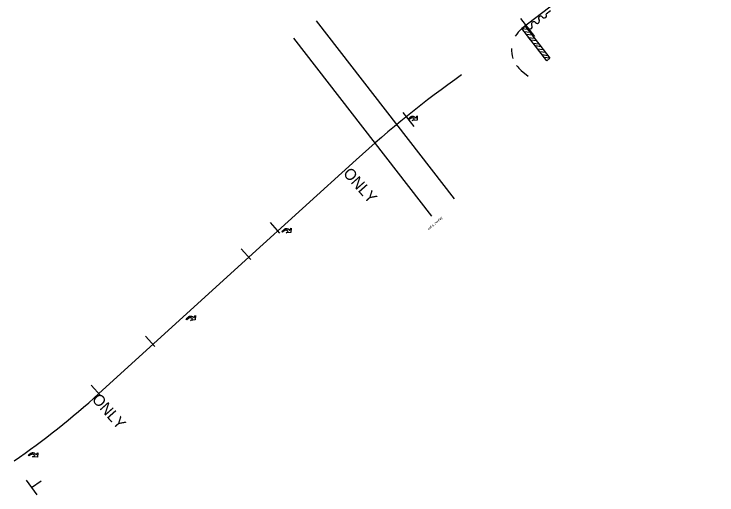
# Model space of a CAD drawing. Extents: x 857071 to 1646387, y 839649 to 1457497.
# Drawn here: x 1638861 to 1639485, y 842405 to 842832 of the extents above; entities that cross this region are included whole.
import ezdxf

# ---------------------------------------------------------------- set-up
doc = ezdxf.new("R2010")
doc.units = 0
for name, color, linetype in [('DEV CRASH CUSHION CELL', 7, 'Continuous'), ('DEV STATIONARY SIGN CELL', 7, 'Continuous'), ('DEV TYPE 3 BARRICADE CELL', 7, 'Continuous'), ('MARK RIGHT ONLY RIGHT SYMBOL CELL', 7, 'Continuous'), ('Prop Mkg 3ft Min Skp 9ft Wide White', 7, 'Continuous'), ('Prop Mkg Solid White Edge Line', 7, 'Continuous'), ('Prop Mkg Solid White Wide Lane Line', 7, 'Continuous'), ('Scratch_Level_0', 7, 'Continuous'), ('Scratch_Level_1', 7, 'Continuous'), ('Scratch_Level_2', 7, 'Continuous'), ('Scratch_Level_3', 7, 'Continuous'), ('Scratch_Level_4', 7, 'Continuous')]:
    doc.layers.add(name, color=color, linetype=linetype)

msp = doc.modelspace()

# ---------------------------------------------------------------- linework, layer by layer
at = {"layer": 'DEV CRASH CUSHION CELL'}
msp.add_line((1639337.59, 842834.49), (1639333.63, 842831.43), dxfattribs=at)
for centre, start, end in [((1639328.89, 842827.76), 37.7072, 217.7072), ((1639332.05, 842830.21), 217.7072, 37.7072), ((1639319.39, 842820.42), 217.7072, 37.7072), ((1639322.56, 842822.87), 37.7072, 217.7072), ((1639325.72, 842825.32), 217.7072, 37.7072)]:
    msp.add_arc(centre, 2, start, end, dxfattribs=at)
at = {"layer": 'DEV STATIONARY SIGN CELL'}
for p, q in [((1638872.01, 842417.87), (1638881.41, 842404.67)), ((1638876.75, 842411.22), (1638885.3, 842417.3))]:
    msp.add_line(p, q, dxfattribs=at)
at = {"layer": 'DEV TYPE 3 BARRICADE CELL'}
for p, q in [((1639312.16, 842818.62), (1639315, 842820.83)), ((1639317.17, 842818.03), (1639312.16, 842818.62)), ((1639312.2, 842818.66), (1639315, 842820.83)), ((1639334.25, 842790.22), (1639312.2, 842818.66)), ((1639314.14, 842816.06), (1639319.16, 842815.47)), ((1639316.12, 842813.5), (1639314.14, 842816.06)), ((1639315, 842820.83), (1639317.17, 842818.03)), ((1639315, 842820.83), (1639337.05, 842792.39)), ((1639319.16, 842815.47), (1639321.14, 842812.91)), ((1639321.14, 842812.91), (1639316.12, 842813.5)), ((1639318.11, 842810.94), (1639323.13, 842810.35)), ((1639320.09, 842808.38), (1639318.11, 842810.94)), ((1639323.13, 842810.35), (1639325.11, 842807.79)), ((1639325.11, 842807.79), (1639320.09, 842808.38)), ((1639322.07, 842805.82), (1639327.09, 842805.23)), ((1639324.06, 842803.27), (1639322.07, 842805.82)), ((1639329.08, 842802.67), (1639324.06, 842803.27)), ((1639327.09, 842805.23), (1639329.08, 842802.67)), ((1639326.04, 842800.71), (1639331.1, 842800.07)), ((1639328.03, 842798.15), (1639326.04, 842800.71)), ((1639333.08, 842797.51), (1639328.03, 842798.15)), ((1639331.1, 842800.07), (1639333.08, 842797.51)), ((1639330.01, 842795.59), (1639335.07, 842794.95)), ((1639331.99, 842793.03), (1639330.01, 842795.59)), ((1639337.05, 842792.39), (1639331.99, 842793.03)), ((1639337.05, 842792.39), (1639334.25, 842790.22)), ((1639335.07, 842794.95), (1639337.05, 842792.39))]:
    msp.add_line(p, q, dxfattribs=at)
at = {"layer": 'MARK RIGHT ONLY RIGHT SYMBOL CELL'}
for points in [[(1639211.7, 842737.61), (1639211.03, 842738.36), (1639212.96, 842740.08), (1639213.34, 842740.38), (1639213.65, 842740.57), (1639214.03, 842740.74), (1639214.39, 842740.83), (1639214.69, 842740.87), (1639215.13, 842740.87), (1639215.46, 842740.83), (1639215.84, 842740.77), (1639216.27, 842740.63), (1639216.58, 842740.48), (1639216.95, 842740.24), (1639217.4, 842739.86), (1639217.94, 842739.26), (1639219.17, 842741.25), (1639219.12, 842737.42), (1639214.74, 842737.08), (1639216.75, 842738.2), (1639216.31, 842738.7), (1639216.04, 842738.97), (1639215.74, 842739.16), (1639215.47, 842739.28), (1639215.09, 842739.4), (1639214.79, 842739.46), (1639214.36, 842739.43), (1639213.96, 842739.32), (1639213.58, 842739.18), (1639213.13, 842738.89)], [(1639099.62, 842637.92), (1639098.95, 842638.67), (1639100.88, 842640.39), (1639101.26, 842640.69), (1639101.57, 842640.88), (1639101.95, 842641.05), (1639102.31, 842641.14), (1639102.61, 842641.18), (1639103.05, 842641.18), (1639103.38, 842641.14), (1639103.76, 842641.08), (1639104.19, 842640.94), (1639104.5, 842640.79), (1639104.87, 842640.55), (1639105.32, 842640.17), (1639105.86, 842639.57), (1639107.09, 842641.56), (1639107.04, 842637.73), (1639102.66, 842637.39), (1639104.67, 842638.51), (1639104.23, 842639.01), (1639103.96, 842639.28), (1639103.66, 842639.47), (1639103.39, 842639.59), (1639103.01, 842639.71), (1639102.71, 842639.77), (1639102.28, 842639.74), (1639101.88, 842639.63), (1639101.5, 842639.49), (1639101.05, 842639.2)], [(1639014.69, 842560.2), (1639014.03, 842560.95), (1639015.96, 842562.66), (1639016.33, 842562.96), (1639016.64, 842563.16), (1639017.02, 842563.32), (1639017.38, 842563.41), (1639017.69, 842563.45), (1639018.12, 842563.46), (1639018.45, 842563.42), (1639018.83, 842563.35), (1639019.27, 842563.21), (1639019.57, 842563.06), (1639019.95, 842562.83), (1639020.39, 842562.45), (1639020.93, 842561.85), (1639022.16, 842563.84), (1639022.12, 842560), (1639017.73, 842559.67), (1639019.74, 842560.79), (1639019.3, 842561.29), (1639019.04, 842561.55), (1639018.74, 842561.75), (1639018.46, 842561.87), (1639018.08, 842561.99), (1639017.78, 842562.04), (1639017.36, 842562.02), (1639016.95, 842561.91), (1639016.57, 842561.77), (1639016.12, 842561.47)], [(1638874.51, 842439.37), (1638873.95, 842440.2), (1638876.08, 842441.65), (1638876.49, 842441.9), (1638876.82, 842442.05), (1638877.22, 842442.17), (1638877.59, 842442.22), (1638877.9, 842442.22), (1638878.33, 842442.17), (1638878.65, 842442.08), (1638879.02, 842441.97), (1638879.43, 842441.78), (1638879.72, 842441.59), (1638880.06, 842441.31), (1638880.45, 842440.88), (1638880.91, 842440.21), (1638882.39, 842442.03), (1638881.85, 842438.23), (1638877.46, 842438.46), (1638879.6, 842439.32), (1638879.22, 842439.87), (1638879, 842440.16), (1638878.72, 842440.39), (1638878.47, 842440.55), (1638878.1, 842440.72), (1638877.81, 842440.8), (1638877.39, 842440.84), (1638876.97, 842440.78), (1638876.58, 842440.68), (1638876.1, 842440.45)]]:
    msp.add_lwpolyline(points, close=True, dxfattribs=at)
at = {"layer": 'Prop Mkg 3ft Min Skp 9ft Wide White'}
msp.add_line((1638936.41, 842494.6), (1639069.61, 842615.67), dxfattribs=at)
msp.add_arc((1638449.18, 843030.65), 724.39, 304.66314, 312.26851, dxfattribs=at)
at = {"layer": 'Prop Mkg Solid White Edge Line'}
for p, q in [((1639485.3, 842952.48), (1639312.2, 842818.66)), ((1639311.51, 842781.56), (1639317.69, 842776.4))]:
    msp.add_line(p, q, dxfattribs=at)
for start, end in [(127.7072, 149.42449), (176.84294, 198.62335), (215.78227, 230.15459)]:
    msp.add_arc((1639326.76, 842799.83), 23.8, start, end, dxfattribs=at)
at = {"layer": 'Prop Mkg Solid White Wide Lane Line'}
msp.add_line((1639069.61, 842615.67), (1639164.86, 842702.25), dxfattribs=at)
msp.add_arc((1639846.14, 841952.7), 1012.9, 125.45872, 132.26851, dxfattribs=at)
at = {"layer": 'Scratch_Level_0'}
msp.add_line((1639206.3, 842744.22), (1639216.25, 842731.91), dxfattribs=at)
at = {"layer": 'Scratch_Level_1'}
msp.add_line((1639129.31, 842825.55), (1639251.96, 842667.58), dxfattribs=at)
at = {"layer": 'Scratch_Level_2'}
msp.add_line((1639323.56, 842811.79), (1639311.3, 842827.59), dxfattribs=at)
at = {"layer": 'Scratch_Level_3'}
msp.add_line((1639232.21, 842652.25), (1639109.56, 842810.22), dxfattribs=at)
at = {"layer": 'Scratch_Level_4'}
for p, q in [((1639097.32, 842637.22), (1639088.79, 842646.61)), ((1639071.42, 842613.68), (1639062.89, 842623.07)), ((1638986.32, 842536.33), (1638977.79, 842545.72)), ((1638938.22, 842492.61), (1638929.69, 842502))]:
    msp.add_line(p, q, dxfattribs=at)

# ---------------------------------------------------------------- texts
at = {"layer": 'MARK RIGHT ONLY RIGHT SYMBOL CELL'}
for p in [(1639152.73, 842689.79), (1638929.66, 842489.19)]:
    msp.add_text('ONLY', height=10, rotation=311.6516, dxfattribs=at).set_placement(p)
at = {"layer": 'Scratch_Level_3'}
msp.add_text('mill & overlay', height=2, rotation=41.65315, dxfattribs=at).set_placement((1639229.54, 842639.59))

doc.saveas('drawing.dxf')
